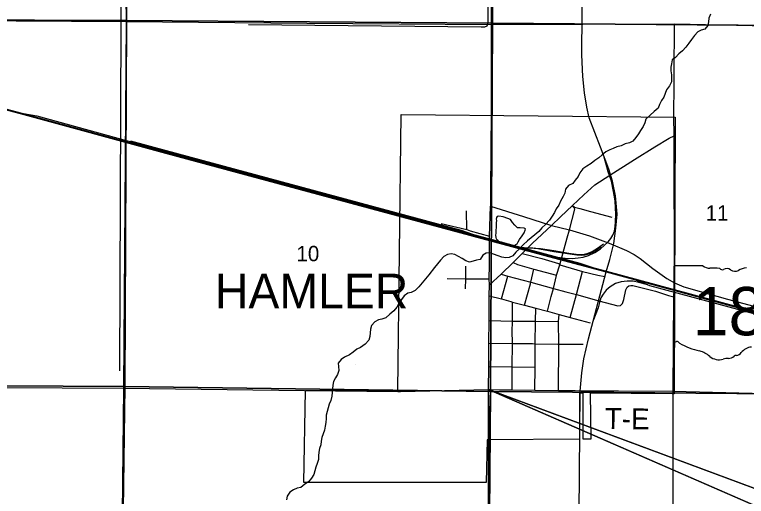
# Model space of a CAD drawing. Extents: x -6.2 to 37.4, y 0.2 to 22.2.
# Drawn here: x 5.556 to 6.554, y 16.426 to 17.083 of the extents above; entities that cross this region are included whole.
import ezdxf

# ---------------------------------------------------------------- set-up
doc = ezdxf.new("R2010")
doc.units = 0
for name, color, linetype in [('GM_X_City_Street', 7, 'Continuous'), ('GM_X_Corporation', 7, 'Continuous'), ('GM_X_Corporation_Text', 7, 'Continuous'), ('GM_X_County_Road', 7, 'Continuous'), ('GM_X_Minor_Lake', 7, 'Continuous'), ('GM_X_Minor_River', 7, 'Continuous'), ('GM_X_Rail_Line', 7, 'Continuous'), ('GM_X_Section', 7, 'Continuous'), ('GM_X_Section_Text', 7, 'Continuous'), ('GM_X_State_Location', 7, 'Continuous'), ('GM_X_State_Route', 7, 'Continuous'), ('GM_X_State_Shield', 7, 'Continuous'), ('GM_X_Township_Road', 7, 'Continuous'), ('GM_X_Township_Road_Text', 7, 'Continuous'), ('SH_Border', 7, 'Continuous'), ('SH_Data', 7, 'Continuous')]:
    doc.layers.add(name, color=color, linetype=linetype)

msp = doc.modelspace()

# ---------------------------------------------------------------- linework, layer by layer
at = {"layer": 'GM_X_City_Street'}
for p, q in [((6.17254, 16.78951), (6.17238, 16.81508)), ((6.17738, 16.7881), (6.2038, 16.78044)), ((6.2202, 16.69495), (6.22845, 16.72614)), ((6.25146, 16.6865), (6.25941, 16.71574))]:
    msp.add_line(p, q, dxfattribs=at)
for points in [[(6.23594, 16.74449), (6.248, 16.75686), (6.26229, 16.77092), (6.28829, 16.79511), (6.30069, 16.80717), (6.31667, 16.82246), (6.33234, 16.83697), (6.34747, 16.85065), (6.36767, 16.8637), (6.40147, 16.88513), (6.42912, 16.90226), (6.44855, 16.91424), (6.45546, 16.91755)], [(6.29497, 16.72683), (6.29508, 16.72733), (6.29939, 16.74135), (6.30257, 16.75344), (6.30956, 16.77821), (6.31287, 16.78904), (6.31989, 16.8175), (6.31886, 16.82), (6.31667, 16.82246)], [(6.31667, 16.82246), (6.31966, 16.82015), (6.327, 16.81819), (6.34132, 16.81439), (6.37063, 16.80656)], [(6.13761, 16.79807), (6.17254, 16.78951), (6.17738, 16.7881)], [(6.248, 16.75686), (6.27481, 16.74993), (6.29762, 16.74346), (6.29939, 16.74135)], [(6.17069, 16.70893), (6.17123, 16.72222), (6.17115, 16.73981)], [(6.20341, 16.71423), (6.21931, 16.7289), (6.23594, 16.74449)], [(6.23594, 16.74449), (6.24195, 16.74192), (6.26415, 16.73574), (6.29508, 16.72733)], [(6.25941, 16.71574), (6.25994, 16.71769), (6.26415, 16.73574)], [(6.29939, 16.74135), (6.33055, 16.73247), (6.3514, 16.72737), (6.36089, 16.72579)], [(6.21931, 16.7289), (6.22845, 16.72614), (6.25994, 16.71769), (6.29098, 16.70939), (6.30757, 16.70486), (6.32239, 16.70094), (6.35288, 16.6925), (6.37869, 16.68574), (6.38222, 16.68581)], [(6.28272, 16.67813), (6.2879, 16.69852), (6.29098, 16.70939), (6.29497, 16.72683)], [(6.31375, 16.66961), (6.32239, 16.70094), (6.33055, 16.73247)], [(6.14573, 16.72268), (6.17123, 16.72222), (6.20334, 16.72245)], [(6.38222, 16.68581), (6.38507, 16.68881), (6.38691, 16.69426), (6.38968, 16.70732), (6.3916, 16.71124), (6.39382, 16.71293)], [(6.39382, 16.71293), (6.39636, 16.71354), (6.39928, 16.71323), (6.43008, 16.70548), (6.4479, 16.69964), (6.45527, 16.69803)], [(6.20318, 16.69925), (6.2202, 16.69495), (6.23256, 16.69147)], [(6.23256, 16.69147), (6.23494, 16.69081), (6.25146, 16.6865), (6.26674, 16.6822), (6.28272, 16.67813), (6.29846, 16.67391), (6.31375, 16.66961), (6.34102, 16.66262)], [(6.23486, 16.63601), (6.23456, 16.65025), (6.23479, 16.66477), (6.23494, 16.69081)], [(6.26547, 16.57068), (6.26578, 16.60194), (6.26601, 16.63397), (6.26643, 16.66477), (6.26674, 16.6822)], [(6.20295, 16.66546), (6.23479, 16.66477), (6.26643, 16.66477), (6.29785, 16.66423)], [(6.29758, 16.57021), (6.29839, 16.63328), (6.29785, 16.66423), (6.29846, 16.67391)], [(6.23444, 16.57098), (6.23467, 16.60247), (6.2349, 16.63404), (6.23486, 16.63601)], [(6.2028, 16.6345), (6.2349, 16.63404), (6.26206, 16.63398)], [(6.26206, 16.63398), (6.26601, 16.63397), (6.29689, 16.63331)], [(6.29689, 16.63331), (6.29839, 16.63328), (6.33138, 16.63312)], [(6.20257, 16.60278), (6.23467, 16.60247), (6.26578, 16.60194)]]:
    msp.add_lwpolyline(points, dxfattribs=at)
at = {"layer": 'GM_X_Corporation'}
msp.add_lwpolyline([(5.95244, 16.5701), (6.07853, 16.5701), (6.08299, 16.94654), (6.45688, 16.94271), (6.45545, 16.56557), (6.45308, 16.56559), (6.34077, 16.56645), (6.34188, 16.50361), (6.33129, 16.50353), (6.33129, 16.56652), (6.32636, 16.56656), (6.32636, 16.5035), (6.20021, 16.50261), (6.1992, 16.4448), (6.07525, 16.4448), (5.95025, 16.4448)], close=True, dxfattribs=at)
at = {"layer": 'GM_X_County_Road'}
msp.add_line((6.20597, 17.06916), (6.45623, 17.07024), dxfattribs=at)
for points in [[(5.20537, 17.07517), (5.55766, 17.07443), (5.70836, 17.07322), (5.95453, 17.07128), (6.20597, 17.06916)], [(6.45623, 17.07024), (6.71031, 17.0648), (7.20862, 17.05946)]]:
    msp.add_lwpolyline(points, dxfattribs=at)
at = {"layer": 'GM_X_Minor_Lake'}
msp.add_line((6.21256, 16.7948), (6.21239, 16.78664), dxfattribs=at)
msp.add_lwpolyline([(6.21239, 16.78664), (6.21235, 16.78475), (6.21172, 16.78191), (6.21242, 16.77886), (6.21276, 16.77677), (6.21388, 16.77561), (6.21592, 16.77348), (6.21952, 16.77284), (6.22462, 16.77122), (6.22689, 16.77061), (6.23218, 16.76936), (6.23501, 16.76855), (6.23747, 16.76793), (6.24113, 16.77033), (6.24289, 16.77276), (6.24467, 16.77595), (6.24819, 16.78119), (6.25112, 16.78531), (6.25214, 16.7887), (6.25256, 16.79059), (6.25106, 16.79157), (6.24556, 16.79187), (6.24176, 16.79213), (6.23803, 16.79543), (6.23507, 16.79947), (6.23211, 16.80314), (6.22872, 16.80472), (6.2223, 16.80675), (6.21643, 16.808), (6.21395, 16.80729), (6.21316, 16.80598), (6.21274, 16.80371), (6.21308, 16.802), (6.21263, 16.79859), (6.21256, 16.7948)], dxfattribs=at)
at = {"layer": 'GM_X_Minor_River'}
for points in [[(5.69878, 17.44485), (5.70035, 17.06928), (5.69856, 16.59708)], [(6.20111, 17.43298), (6.20148, 17.07336), (6.20103, 17.06957), (6.19983, 17.06694), (6.19677, 17.06586), (6.19221, 17.06557), (5.87457, 17.06865)], [(6.50513, 17.08329), (6.50293, 17.07802), (6.50264, 17.07309), (6.50159, 17.06799), (6.49731, 17.06295), (6.49253, 17.06172), (6.48774, 17.05935), (6.48327, 17.0545), (6.47936, 17.04908), (6.47545, 17.04403), (6.47135, 17.03861), (6.46688, 17.03358), (6.46186, 17.0295), (6.45758, 17.02446), (6.45276, 17.02133), (6.45208, 17.01584), (6.45122, 17.01093), (6.45112, 17.00619), (6.45178, 17.00086), (6.45206, 16.99592), (6.45196, 16.99118), (6.44938, 16.98573), (6.44528, 16.98031), (6.44328, 16.97522), (6.44128, 16.97033)], [(6.44128, 16.97033), (6.43833, 16.96546), (6.43575, 16.96019), (6.43356, 16.9553), (6.42833, 16.95047), (6.4171, 16.94007), (6.41548, 16.93517), (6.41329, 16.93028), (6.40976, 16.92485), (6.40681, 16.91997), (6.40349, 16.91511), (6.3994, 16.91025), (6.3946, 16.90788), (6.38868, 16.90648), (6.38312, 16.90394), (6.3772, 16.90253), (6.3724, 16.90016), (6.36762, 16.89855), (6.36243, 16.89581), (6.35741, 16.89154), (6.35258, 16.88765), (6.34737, 16.88396), (6.34235, 16.87989), (6.33619, 16.87621), (6.33079, 16.87234), (6.32708, 16.8671), (6.32451, 16.86221), (6.32061, 16.85717), (6.31709, 16.85231), (6.31153, 16.84976), (6.30744, 16.84491), (6.30619, 16.83943), (6.30419, 16.83454), (6.30064, 16.82815), (6.29806, 16.8227), (6.29473, 16.81784), (6.29215, 16.81276), (6.28901, 16.80789), (6.28548, 16.80246), (6.28005, 16.79669), (6.27482, 16.79186), (6.27073, 16.78682), (6.26551, 16.78237), (6.26067, 16.77829), (6.25565, 16.77402), (6.24965, 16.76883), (6.2448, 16.76399), (6.23957, 16.75878), (6.23547, 16.75374), (6.23049, 16.75137), (6.22573, 16.75128), (6.22043, 16.75214), (6.21533, 16.75376), (6.20911, 16.75616), (6.20421, 16.75797), (6.19926, 16.75749), (6.19445, 16.75455), (6.19091, 16.74874), (6.18595, 16.7477), (6.18117, 16.74647), (6.17621, 16.74524), (6.17111, 16.74686), (6.16623, 16.74999), (6.16135, 16.75293), (6.15628, 16.7555), (6.15117, 16.75655), (6.1464, 16.7557), (6.14121, 16.75276), (6.13655, 16.74773), (6.13246, 16.74288), (6.12875, 16.73802), (6.12094, 16.72793), (6.11628, 16.72252), (6.11179, 16.71692), (6.10712, 16.71132), (6.10208, 16.70667), (6.09689, 16.70355), (6.09212, 16.7027), (6.08712, 16.69938), (6.08359, 16.69414), (6.08006, 16.68871), (6.07729, 16.68364), (6.07321, 16.67879), (6.0676, 16.67416), (6.06218, 16.66933), (6.05682, 16.66735), (6.05206, 16.66669), (6.04725, 16.66356), (6.0424, 16.65891), (6.04116, 16.65381), (6.04067, 16.6487), (6.04019, 16.64377), (6.03895, 16.63868), (6.03409, 16.63308), (6.02773, 16.62884), (6.02255, 16.62648), (6.01772, 16.62221), (6.0127, 16.61852)], [(6.0127, 16.61852), (6.0058, 16.61562), (6.00098, 16.6123), (5.99728, 16.60744), (5.99756, 16.60269), (5.99783, 16.59756), (5.9962, 16.59209), (5.99363, 16.58721), (5.99068, 16.58215), (5.98982, 16.57723), (5.98915, 16.57231), (5.98905, 16.56719), (5.98857, 16.56227), (5.98712, 16.5566), (5.98474, 16.55134), (5.9835, 16.54643), (5.98206, 16.54134), (5.98082, 16.53643), (5.98073, 16.53169), (5.98005, 16.52658), (5.97957, 16.52128), (5.97832, 16.51599), (5.9767, 16.51109), (5.9747, 16.506), (5.97403, 16.50108), (5.97354, 16.49597), (5.97173, 16.49089), (5.97049, 16.48579), (5.97039, 16.48086), (5.9701, 16.47593), (5.96828, 16.47065), (5.96646, 16.46557), (5.96522, 16.46047), (5.96398, 16.45556), (5.96084, 16.4505), (5.95656, 16.44546), (5.95174, 16.44214), (5.94614, 16.43789), (5.94099, 16.43667), (5.93601, 16.43468), (5.93119, 16.43155), (5.92728, 16.42594), (5.92661, 16.42102)], [(6.02136, 16.60525), (6.02137, 16.60526)]]:
    msp.add_lwpolyline(points, dxfattribs=at)
at = {"layer": 'GM_X_Rail_Line'}
for points in [[(6.31856, 15.3389), (6.32321, 16.06776), (6.32739, 16.56932), (6.32971, 16.59442), (6.3325, 16.61347), (6.33861, 16.64043), (6.36296, 16.73186), (6.36763, 16.74863), (6.37346, 16.77072), (6.37609, 16.79136), (6.37782, 16.81051), (6.3756, 16.83566), (6.37132, 16.85572), (6.36631, 16.872), (6.35505, 16.90208), (6.33963, 16.94196), (6.33622, 16.95652), (6.33343, 16.97605), (6.33111, 16.99836), (6.32971, 17.02811), (6.33343, 17.47435), (6.33417, 17.70742)], [(5.08086, 17.07841), (5.24614, 17.03335), (5.56355, 16.94898), (5.76185, 16.89495), (6.29118, 16.75206), (6.36324, 16.73286), (6.77114, 16.62218), (7.01421, 16.55646), (7.20439, 16.50284), (7.71112, 16.36634), (8.46264, 16.16477), (8.48086, 16.15985)], [(5.08086, 17.07713), (5.24582, 17.03215), (5.56322, 16.94778), (5.76153, 16.89375), (5.76153, 16.89375), (6.29101, 16.75083), (6.36296, 16.73186), (6.77082, 16.62098), (6.77081, 16.62098), (7.01387, 16.55522), (7.20406, 16.50164), (7.7108, 16.36514), (7.71112, 16.36634), (7.7108, 16.36514), (8.46231, 16.16357), (8.48086, 16.15856)], [(5.56769, 16.94786), (5.58573, 16.94469), (5.76218, 16.89615), (6.2915, 16.75327), (6.32685, 16.74384), (6.34323, 16.73819)], [(5.71351, 16.9105), (5.7625, 16.89735), (6.1649, 16.78873), (6.18019, 16.78331)], [(6.29683, 16.75184), (6.30696, 16.75042), (6.3165, 16.75026), (6.32447, 16.751), (6.33146, 16.75215), (6.33869, 16.75437), (6.34732, 16.75848), (6.35513, 16.76349), (6.36532, 16.77294), (6.36894, 16.77763), (6.37174, 16.78215), (6.37428, 16.78758), (6.37519, 16.79358), (6.37576, 16.80007), (6.37617, 16.81068), (6.37568, 16.81914), (6.37486, 16.82892), (6.37289, 16.84134), (6.36993, 16.8558), (6.36565, 16.86855), (6.3636, 16.8752), (6.36024, 16.88823)], [(6.24358, 16.7662), (6.25476, 16.76464), (6.2629, 16.76448), (6.26441, 16.76437)], [(6.26441, 16.76437), (6.27318, 16.76374), (6.29118, 16.76119), (6.31197, 16.75724), (6.32537, 16.7556), (6.3308, 16.75568), (6.33803, 16.75724), (6.34387, 16.75955), (6.35234, 16.76497), (6.35916, 16.77015)], [(6.3562, 16.76604), (6.34823, 16.7607), (6.34403, 16.75831), (6.34001, 16.75659), (6.33376, 16.7547), (6.32858, 16.75412), (6.32266, 16.75453), (6.29159, 16.75938), (6.26441, 16.76437)], [(6.41983, 16.71426), (6.40758, 16.71754), (6.39952, 16.71918), (6.39163, 16.71943), (6.38341, 16.71836), (6.3756, 16.7159), (6.36837, 16.71146), (6.36294, 16.70685), (6.3585, 16.70151), (6.35571, 16.69633), (6.35349, 16.68992), (6.35168, 16.68277), (6.34558, 16.66662)], [(6.40304, 16.72097), (6.42177, 16.71349), (6.77049, 16.61978), (6.89878, 16.58478), (6.91289, 16.58254)]]:
    msp.add_lwpolyline(points, dxfattribs=at)
at = {"layer": 'GM_X_Section'}
for points in [[(5.20682, 17.58263), (5.70428, 17.571), (5.7075, 17.57094), (5.70816, 17.07492), (5.20579, 17.07678)], [(5.7075, 17.57094), (6.20873, 17.56928), (6.20764, 17.07112), (5.70816, 17.07492)], [(6.20873, 17.56928), (6.71428, 17.56583), (6.71052, 17.06693), (6.20764, 17.07112)], [(5.20579, 17.07678), (5.70816, 17.07492), (5.7061, 16.57535), (5.19997, 16.57826)], [(5.70816, 17.07492), (6.20764, 17.07112), (6.20497, 16.56877), (5.7061, 16.57535)], [(6.20764, 17.07112), (6.71052, 17.06693), (6.70936, 16.56455), (6.20497, 16.56877)], [(5.19997, 16.57826), (5.7061, 16.57535), (5.69905, 16.07137), (5.19464, 16.07482)], [(5.7061, 16.57535), (6.20497, 16.56877), (6.20098, 16.06682), (5.69905, 16.07137)], [(6.20497, 16.56877), (6.70936, 16.56455), (6.70367, 16.06302), (6.20098, 16.06682)]]:
    msp.add_lwpolyline(points, close=True, dxfattribs=at)
at = {"layer": 'GM_X_State_Route'}
for p, q in [((6.20709, 17.56607), (6.20597, 17.06916)), ((6.20597, 17.06916), (6.20567, 16.93171)), ((6.2038, 16.78044), (6.2048, 16.82146)), ((6.20369, 16.75321), (6.2038, 16.78044))]:
    msp.add_line(p, q, dxfattribs=at)
for points in [[(6.20567, 16.93171), (6.20563, 16.91797), (6.2048, 16.82146)], [(6.2048, 16.82146), (6.25011, 16.8074), (6.28829, 16.79511), (6.31287, 16.78904), (6.33998, 16.78098), (6.36917, 16.77), (6.39067, 16.76101), (6.40081, 16.75579), (6.40918, 16.75033), (6.4267, 16.73643), (6.44536, 16.72268), (6.45615, 16.71677)], [(6.20234, 16.57137), (6.20257, 16.60278), (6.2028, 16.6345), (6.20295, 16.66546), (6.20318, 16.69925), (6.20341, 16.71423), (6.20334, 16.72245), (6.20364, 16.74096), (6.20369, 16.75321)], [(6.45615, 16.71677), (6.46879, 16.71131), (6.51361, 16.69881)], [(6.51361, 16.69881), (6.52855, 16.69465), (6.59837, 16.67583), (6.65098, 16.66162), (6.70705, 16.64679), (6.89664, 16.59114), (6.96204, 16.5734), (6.99595, 16.56421), (7.20657, 16.55788)], [(6.18807, 14.56397), (6.19173, 15.06016), (6.19455, 15.41396), (6.19571, 15.56327), (6.19964, 16.06397), (6.20331, 16.54154), (6.20234, 16.57137)]]:
    msp.add_lwpolyline(points, dxfattribs=at)
at = {"layer": 'GM_X_State_Shield'}
for p, q in [((6.455, 16.73841), (6.455, 16.63835)), ((6.49491, 16.74013), (6.4563, 16.74013))]:
    msp.add_line(p, q, dxfattribs=at)
for centre, radius, start, end in [((6.45651, 16.73862), 0.00153, 98.1301, 188.1301), ((6.5041, 16.75174), 0.01481, 231.61951, 271.11188), ((6.50901, 16.68395), 0.05318, 80.48669, 94.98827), ((6.52109, 16.73914), 0.00427, 219.79206, 297.10237), ((6.52736, 16.72757), 0.00889, 54.46668, 119.14113), ((6.53883, 16.74344), 0.01069, 233.85621, 294.82819), ((6.5577, 16.70957), 0.02813, 97.34618, 120.76885), ((6.45652, 16.63813), 0.00154, 171.95839, 258.30661), ((6.45676, 16.64836), 0.01176, 267.33899, 280.60386), ((6.45916, 16.63257), 0.00424, 29.74838, 93.27175), ((6.51269, 16.72247), 0.10096, 240.41292, 257.1985), ((6.56245, 16.61025), 0.01915, 94.40312, 142.57675), ((6.48259, 16.59339), 0.03159, 47.18416, 75.83597), ((6.51676, 16.63208), 0.02004, 230.70037, 286.29184), ((6.5298, 16.62458), 0.01068, 268.77702, 315.54927), ((6.53947, 16.61489), 0.00301, 65.75173, 132.64842), ((6.53818, 16.62865), 0.0113, 282.87319, 323.27711), ((6.52834, 16.59748), 0.01647, 85.69512, 111.20995)]:
    msp.add_arc(centre, radius, start, end, dxfattribs=at)
at = {"layer": 'GM_X_Township_Road'}
for p, q in [((5.70836, 17.07322), (5.70306, 17.56995)), ((5.70476, 16.57329), (5.70836, 17.07322)), ((6.45577, 16.92016), (6.4554, 16.92974)), ((5.69937, 16.06826), (5.70476, 16.57329)), ((6.08201, 16.56882), (6.20234, 16.57137)), ((6.20234, 16.57137), (6.21716, 16.57119)), ((6.33051, 16.56983), (6.3404, 16.5698))]:
    msp.add_line(p, q, dxfattribs=at)
for points in [[(6.4554, 16.92974), (6.45531, 16.93214), (6.45623, 17.07024)], [(6.45615, 16.71677), (6.45546, 16.91755), (6.45577, 16.92016)], [(6.45412, 16.56929), (6.45527, 16.69803), (6.45615, 16.71677)], [(5.08086, 16.57706), (5.20026, 16.5759), (5.70476, 16.57329), (5.95103, 16.57029)], [(5.95103, 16.57029), (6.07835, 16.56874), (6.08201, 16.56882)], [(6.21716, 16.57119), (6.23444, 16.57098), (6.26547, 16.57068), (6.29758, 16.57021), (6.32067, 16.56993)], [(6.32067, 16.56993), (6.32853, 16.56983), (6.33051, 16.56983)], [(6.3404, 16.5698), (6.37946, 16.56968), (6.45412, 16.56929)], [(6.45271, 16.06148), (6.45428, 16.25883), (6.45412, 16.56929)], [(6.45412, 16.56929), (6.70533, 16.56267), (6.95642, 16.55946), (6.95929, 16.56132), (6.96124, 16.56413), (6.96204, 16.5734)]]:
    msp.add_lwpolyline(points, dxfattribs=at)
at = {"layer": 'SH_Border'}
for p, q in [((6.20234, 16.57137), (8.99438, 15.5335)), ((8.99438, 15.3553), (6.20234, 16.57137))]:
    msp.add_line(p, q, dxfattribs=at)
at = {"layer": 'SH_Data'}
msp.add_lwpolyline([(6.18807, 14.56397), (6.19254, 15.16158), (6.19541, 15.52453), (6.20207, 16.38039), (6.20234, 16.57137)], dxfattribs=at)
msp.add_lwpolyline([(8.99438, 15.5335), (6.20234, 16.57137), (8.99438, 15.3553)], close=True, dxfattribs=at)

# ---------------------------------------------------------------- texts
at = {"layer": 'GM_X_Corporation_Text'}
msp.add_text('HAMLER', height=0.047348, rotation=0.00001, dxfattribs=at).set_placement((5.82892, 16.68204))
at = {"layer": 'GM_X_Section_Text'}
for s, p in [('11', (6.4985, 16.80181)), ('10', (5.94017, 16.74639))]:
    msp.add_text(s, height=0.020928, rotation=0.00001, dxfattribs=at).set_placement(p)
at = {"layer": 'GM_X_State_Location'}
msp.add_text('18', height=0.0000947, rotation=0.00001, dxfattribs=at).set_placement((6.49558, 16.67483))
for s in ['s', 'r']:
    msp.add_text(s, height=0.0000947, dxfattribs=at).set_placement((6.51943, 16.68172))
at = {"layer": 'GM_X_State_Shield'}
msp.add_text('18', height=0.065918, dxfattribs=at).set_placement((6.48086, 16.6454))
at = {"layer": 'GM_X_Township_Road_Text'}
msp.add_text('T-E', height=0.028409, rotation=359.11906, dxfattribs=at).set_placement((6.36067, 16.51795))

doc.saveas('drawing.dxf')
